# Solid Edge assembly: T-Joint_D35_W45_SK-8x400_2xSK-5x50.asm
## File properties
Author: fknapp
Template: iso metric assembly.asm
Last saved by: fknapp
Revision: 6
Application: Solid Edge
Username: fknapp
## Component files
T-Joint_D35_W45.par
SK Knapp Schraube 8x400_ohne_Gewinde_22042020.par
SK Schraube 5x50_ohne_Gewinde.par
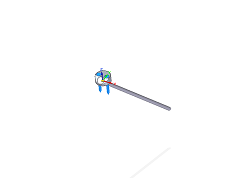
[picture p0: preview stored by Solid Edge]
